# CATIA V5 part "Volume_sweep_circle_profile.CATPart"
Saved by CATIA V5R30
Part number: Part1
Bounding box of the stored display mesh (mm): x -183.601 to 0, y -90.736 to 90.736, z -90.733 to 90.733
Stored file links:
  D:\PROJECTS\CATIA V56R 2020\Resources\Parts File\c17_catia_v6_6r2020_prt\Volume_sweep_circle_profile.CATPart
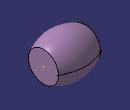
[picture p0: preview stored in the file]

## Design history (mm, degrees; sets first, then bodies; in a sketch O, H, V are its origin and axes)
Set1
  Sketch1 on xy-plane, origin (0, 0, 0), H (1, 0, 0), V (0, 1, 0)
    line L1 (0, 0) -> (-183.1008, 0)
    horizontal: L1 H
  Sketch2 on xy-plane, origin (0, 0, 0), H (1, 0, 0), V (0, 1, 0)
    spline S1 through (0, 65.5148) (-89.6654, 90.7245) (-183.6013, 65.5148)
    point P1 (0, 65.5148)
    coincidence: P1 V
  Sweep1: type Circle, Guide Sketch1, Reference Sketch2, Radius 55
Body1 (main body)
